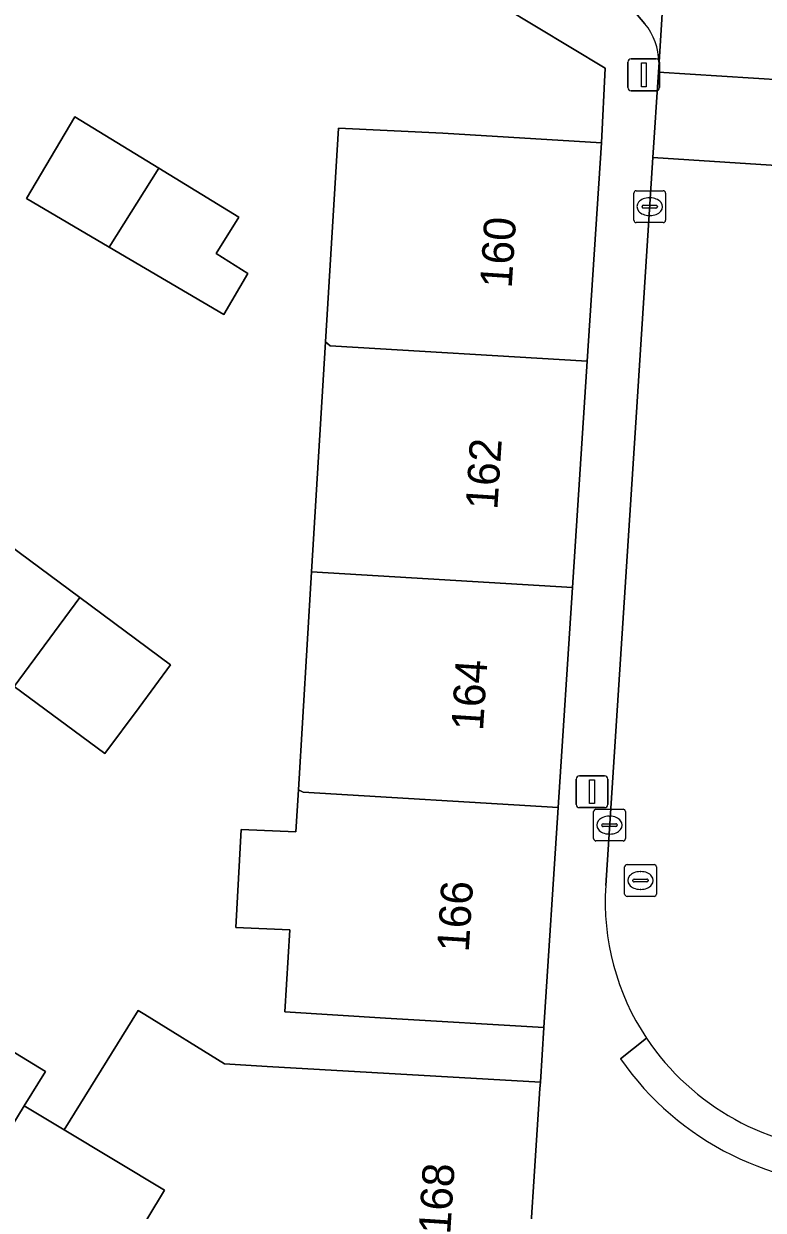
# Model space of a CAD drawing. Extents: x 160102 to 160934, y 382045 to 382923.
# Drawn here: x 160536.3 to 160559.57, y 382504.65 to 382542.01 of the extents above; entities that cross this region are included whole.
import ezdxf

# ---------------------------------------------------------------- set-up
doc = ezdxf.new("R2010")
doc.units = 0
for name, color, linetype in [('IMGEO_Erf', 7, 'Continuous'), ('IMGEO_Kolk', 7, 'Continuous'), ('IMGEO_Lichtmast', 7, 'Continuous'), ('IMGEO_Pand', 7, 'Continuous'), ('IMGEO_Pand_nummerreeks', 7, 'Continuous'), ('IMGEO_Parkeervlak_open', 7, 'Continuous'), ('IMGEO_Rijbaan_lokaal_open', 7, 'Continuous'), ('IMGEO_Rioolput', 7, 'Continuous'), ('IMGEO_Voetpad_open', 7, 'Continuous')]:
    doc.layers.add(name, color=color, linetype=linetype)

msp = doc.modelspace()

# ---------------------------------------------------------------- linework, layer by layer
at = {"layer": 'IMGEO_Erf'}
for points in [[(160544.676, 382513.487), (160542.97, 382513.555), (160543.147, 382516.638), (160544.862, 382516.571), (160544.942, 382517.894), (160545.358, 382524.757), (160545.796, 382532), (160546.203, 382538.72), (160549.487, 382538.567), (160554.477, 382538.267), (160554.602, 382540.614), (160550.277, 382543.226)], [(160533.952, 382510.872), (160536.981, 382509.028), (160536.316, 382507.94), (160537.577, 382507.182), (160539.903, 382510.942), (160540.111, 382510.813), (160542.623, 382509.26), (160543.965, 382509.183), (160552.558, 382508.69), (160552.672, 382510.406), (160547.682, 382510.707), (160544.519, 382510.898), (160544.676, 382513.487)]]:
    msp.add_lwpolyline(points, dxfattribs=at)
for points in [[(160536.39, 382536.513), (160537.908, 382539.086), (160540.55, 382537.465), (160543.07, 382535.92), (160542.351, 382534.777), (160543.356, 382534.145), (160542.594, 382532.854), (160538.987, 382534.981)], [(160533.142, 382523.268), (160534.176, 382524.662), (160535.214, 382526.061), (160538.069, 382523.943), (160540.923, 382521.825), (160539.928, 382520.484), (160538.851, 382519.032), (160535.996, 382521.15)]]:
    msp.add_lwpolyline(points, close=True, dxfattribs=at)
at = {"layer": 'IMGEO_Kolk'}
for p, q in [((160555.573, 382536.753), (160556.425, 382536.753)), ((160555.498, 382535.827), (160555.498, 382536.679)), ((160555.986, 382536.533), (160556.011, 382536.533)), ((160556.499, 382536.679), (160556.499, 382535.827)), ((160555.757, 382536.247), (160555.757, 382536.259)), ((160556.195, 382536.21), (160555.797, 382536.21)), ((160555.8, 382536.296), (160556.198, 382536.296)), ((160556.009, 382535.973), (160555.984, 382535.973)), ((160556.241, 382536.259), (160556.241, 382536.247)), ((160556.425, 382535.753), (160555.573, 382535.753)), ((160554.308, 382517.281), (160555.16, 382517.281)), ((160554.233, 382516.355), (160554.233, 382517.207)), ((160554.721, 382517.061), (160554.746, 382517.061)), ((160555.234, 382517.207), (160555.234, 382516.355)), ((160554.492, 382516.775), (160554.492, 382516.787)), ((160554.93, 382516.738), (160554.532, 382516.738)), ((160554.535, 382516.824), (160554.933, 382516.824)), ((160554.976, 382516.787), (160554.976, 382516.775)), ((160555.16, 382516.281), (160554.308, 382516.281)), ((160554.744, 382516.501), (160554.719, 382516.501))]:
    msp.add_line(p, q, dxfattribs=at)
for points in [[(160555.573, 382536.753), (160556.425, 382536.753)], [(160555.498, 382535.827), (160555.498, 382536.679)], [(160556.499, 382536.679), (160556.499, 382535.827)], [(160556.425, 382535.753), (160555.573, 382535.753)], [(160554.308, 382517.281), (160555.16, 382517.281)], [(160554.233, 382516.355), (160554.233, 382517.207)], [(160555.234, 382517.207), (160555.234, 382516.355)], [(160555.16, 382516.281), (160554.308, 382516.281)]]:
    msp.add_lwpolyline(points, dxfattribs=at)
for centre, radius, start, end in [((160555.575, 382536.677), 0.0765, 91.552, 178.448), ((160555.575, 382536.677), 0.0765, 91.552, 178.448), ((160556.423, 382536.677), 0.0765, 1.552, 88.448), ((160556.423, 382536.677), 0.0765, 1.552, 88.448), ((160555.797, 382536.256), 0.0403, 85.8775, 175.7526), ((160555.794, 382536.246), 0.0366, 178.938, 274.7102), ((160556.198, 382536.253), 0.043, 264.8664, 352.4533), ((160556.202, 382536.258), 0.0386, 1.7309, 96.639), ((160555.575, 382535.829), 0.0765, 181.552, 268.448), ((160555.575, 382535.829), 0.0765, 181.552, 268.448), ((160556.423, 382535.829), 0.0765, 271.552, 358.448), ((160556.423, 382535.829), 0.0765, 271.552, 358.448), ((160554.31, 382517.205), 0.0765, 91.552, 178.448), ((160554.31, 382517.205), 0.0765, 91.552, 178.448), ((160555.158, 382517.205), 0.0765, 1.552, 88.448), ((160555.158, 382517.205), 0.0765, 1.552, 88.448), ((160554.532, 382516.784), 0.0403, 85.8775, 175.7526), ((160554.529, 382516.774), 0.0366, 178.938, 274.7102), ((160554.933, 382516.781), 0.043, 264.8664, 352.4533), ((160554.937, 382516.786), 0.0386, 1.7309, 96.639), ((160554.31, 382516.357), 0.0765, 181.552, 268.448), ((160554.31, 382516.357), 0.0765, 181.552, 268.448), ((160555.158, 382516.357), 0.0765, 271.552, 358.448), ((160555.158, 382516.357), 0.0765, 271.552, 358.448)]:
    msp.add_arc(centre, radius, start, end, dxfattribs=at)
for centre, major_axis, ratio, start_param, end_param in [((160555.985, 382536.253), (-0.387, 0.002), 0.722429, 4.712389, 7.853982), ((160556.01, 382536.253), (-0.39, 0.002), 0.717154, 1.570796, 4.712389), ((160554.72, 382516.781), (-0.387, 0.002), 0.722429, 4.712389, 7.853982), ((160554.745, 382516.781), (-0.39, 0.002), 0.717154, 1.570796, 4.712389)]:
    msp.add_ellipse(centre, major_axis=major_axis, ratio=ratio, start_param=start_param, end_param=end_param, dxfattribs=at)
at = {"layer": 'IMGEO_Lichtmast'}
for p, q in [((160555.315, 382540.005), (160555.315, 382540.805)), ((160555.315, 382540.805), (160555.315, 382540.005)), ((160555.415, 382540.905), (160556.205, 382540.905)), ((160556.205, 382540.905), (160555.415, 382540.905)), ((160556.305, 382540.805), (160556.305, 382540.005)), ((160556.305, 382540.005), (160556.305, 382540.805)), ((160556.205, 382539.905), (160555.415, 382539.905)), ((160555.415, 382539.905), (160556.205, 382539.905)), ((160553.688, 382517.432), (160553.688, 382518.232)), ((160553.688, 382518.232), (160553.688, 382517.432)), ((160553.788, 382518.332), (160554.578, 382518.332)), ((160554.578, 382518.332), (160553.788, 382518.332)), ((160554.678, 382518.232), (160554.678, 382517.432)), ((160554.678, 382517.432), (160554.678, 382518.232)), ((160554.578, 382517.332), (160553.788, 382517.332)), ((160553.788, 382517.332), (160554.578, 382517.332))]:
    msp.add_line(p, q, dxfattribs=at)
for points in [[(160555.735, 382540.78), (160555.885, 382540.78), (160555.885, 382540.03), (160555.735, 382540.03), (160555.735, 382540.78)], [(160554.108, 382518.207), (160554.258, 382518.207), (160554.258, 382517.457), (160554.108, 382517.457), (160554.108, 382518.207)]]:
    msp.add_lwpolyline(points, dxfattribs=at)
for centre, start, end in [((160555.415, 382540.805), 90, 180), ((160555.415, 382540.805), 90, 180), ((160556.205, 382540.805), 0, 90), ((160556.205, 382540.805), 360, 90), ((160555.415, 382540.005), 180, 270), ((160555.415, 382540.005), 180, 270), ((160556.205, 382540.005), 270, 0), ((160556.205, 382540.005), 270, 0), ((160553.788, 382518.232), 90, 180), ((160553.788, 382518.232), 90, 180), ((160554.578, 382518.232), 0, 90), ((160554.578, 382518.232), 360, 90), ((160553.788, 382517.432), 180, 270), ((160553.788, 382517.432), 180, 270), ((160554.578, 382517.432), 270, 0), ((160554.578, 382517.432), 270, 0)]:
    msp.add_arc(centre, 0.1, start, end, dxfattribs=at)
at = {"layer": 'IMGEO_Pand'}
for points in [[(160538.987, 382534.981), (160540.55, 382537.465), (160537.908, 382539.086), (160536.39, 382536.513)], [(160554.477, 382538.267), (160549.487, 382538.567), (160546.203, 382538.72), (160545.796, 382532), (160545.938, 382531.875), (160554.031, 382531.388)], [(160538.987, 382534.981), (160542.594, 382532.854), (160543.356, 382534.145), (160542.351, 382534.777), (160543.07, 382535.92), (160540.55, 382537.465)], [(160554.031, 382531.388), (160545.938, 382531.875), (160545.796, 382532), (160545.358, 382524.757), (160553.57, 382524.261)], [(160538.069, 382523.943), (160535.214, 382526.061), (160534.176, 382524.662), (160533.142, 382523.268), (160535.996, 382521.15)], [(160553.57, 382524.261), (160545.358, 382524.757), (160544.942, 382517.894), (160545.09, 382517.821), (160553.121, 382517.336)], [(160540.923, 382521.825), (160538.069, 382523.943), (160535.996, 382521.15), (160538.851, 382519.032), (160539.928, 382520.484)], [(160553.121, 382517.336), (160545.09, 382517.821), (160544.942, 382517.894), (160544.862, 382516.571), (160543.147, 382516.638), (160542.97, 382513.555), (160544.676, 382513.487), (160544.519, 382510.898), (160547.682, 382510.707), (160552.672, 382510.406)], [(160552.545, 382508.49), (160552.558, 382508.69), (160543.965, 382509.183), (160542.623, 382509.26), (160540.111, 382510.813), (160539.903, 382510.942), (160537.577, 382507.182), (160540.727, 382505.291), (160539.679, 382503.544), (160541.371, 382502.756), (160541.507, 382502.748), (160543.903, 382502.6), (160543.88, 382502.225), (160544.098, 382502.211), (160544.087, 382502.042), (160552.091, 382501.5)], [(160536.981, 382509.028), (160533.952, 382510.872), (160532.291, 382508.224), (160535.085, 382506.529), (160535.354, 382506.366), (160536.316, 382507.94)], [(160537.577, 382507.182), (160536.316, 382507.94), (160535.354, 382506.366), (160535.085, 382506.529), (160534.306, 382505.245), (160538.993, 382502.401), (160539.679, 382503.544), (160540.727, 382505.291)]]:
    msp.add_lwpolyline(points, close=True, dxfattribs=at)
at = {"layer": 'IMGEO_Parkeervlak_open'}
for points in [[(160556.291, 382540.798), (160558.072, 382569.42)], [(160554.93, 382543.102), (160555.849, 382542.013)]]:
    msp.add_lwpolyline(points, dxfattribs=at)
msp.add_arc((160554.275, 382540.753), 2.016, 1.2884, 38.693, dxfattribs=at)
at = {"layer": 'IMGEO_Rijbaan_lokaal_open'}
for points in [[(160556.271, 382540.489), (160562.258, 382540.108), (160564.68, 382581.638), (160558.845, 382582.037), (160558.793, 382580.934), (160558.072, 382569.42), (160556.291, 382540.798)], [(160556.271, 382540.489), (160556.099, 382537.796), (160562.086, 382537.415), (160562.258, 382540.108)]]:
    msp.add_lwpolyline(points, close=True, dxfattribs=at)
msp.add_lwpolyline([(160560.981, 382520.071), (160562.086, 382537.415), (160556.099, 382537.796), (160555.566, 382529.462), (160554.615, 382514.878)], dxfattribs=at)
for centre, radius, start, end in [((160562.378, 382514.373), 7.779, 176.2803, 213.5691), ((160562.563, 382514.541), 8.026, 213.8343, 268.175)]:
    msp.add_arc(centre, radius, start, end, dxfattribs=at)
at = {"layer": 'IMGEO_Rioolput'}
for p, q in [((160555.209, 382514.612), (160555.209, 382515.464)), ((160555.284, 382515.538), (160556.136, 382515.538)), ((160556.21, 382515.464), (160556.21, 382514.612)), ((160555.468, 382515.032), (160555.468, 382515.044)), ((160555.511, 382515.081), (160555.909, 382515.081)), ((160555.697, 382515.318), (160555.722, 382515.318)), ((160555.952, 382515.044), (160555.952, 382515.032)), ((160555.906, 382514.995), (160555.508, 382514.995)), ((160555.72, 382514.758), (160555.695, 382514.758)), ((160556.136, 382514.538), (160555.284, 382514.538))]:
    msp.add_line(p, q, dxfattribs=at)
for points in [[(160555.209, 382514.612), (160555.209, 382515.464)], [(160555.284, 382515.538), (160556.136, 382515.538)], [(160556.21, 382515.464), (160556.21, 382514.612)], [(160556.136, 382514.538), (160555.284, 382514.538)]]:
    msp.add_lwpolyline(points, dxfattribs=at)
for centre, radius, start, end in [((160555.286, 382515.462), 0.0765, 91.552, 178.448), ((160555.286, 382515.462), 0.0765, 91.552, 178.448), ((160556.134, 382515.462), 0.0765, 1.552, 88.448), ((160556.134, 382515.462), 0.0765, 1.552, 88.448), ((160555.508, 382515.041), 0.0403, 85.8775, 175.7526), ((160555.505, 382515.031), 0.0366, 178.938, 274.7102), ((160555.909, 382515.038), 0.043, 264.8664, 352.4533), ((160555.913, 382515.043), 0.0386, 1.7309, 96.639), ((160555.286, 382514.614), 0.0765, 181.552, 268.448), ((160555.286, 382514.614), 0.0765, 181.552, 268.448), ((160556.134, 382514.614), 0.0765, 271.552, 358.448), ((160556.134, 382514.614), 0.0765, 271.552, 358.448)]:
    msp.add_arc(centre, radius, start, end, dxfattribs=at)
for centre, major_axis, ratio, start_param, end_param in [((160555.696, 382515.038), (-0.387, 0.002), 0.722429, 4.712389, 7.853982), ((160555.721, 382515.038), (-0.39, 0.002), 0.717154, 1.570796, 4.712389)]:
    msp.add_ellipse(centre, major_axis=major_axis, ratio=ratio, start_param=start_param, end_param=end_param, dxfattribs=at)
at = {"layer": 'IMGEO_Voetpad_open'}
for points in [[(160556.132, 382586.617), (160557.538, 382586.493), (160557.335, 382584.697), (160556.273, 382576.99), (160555.417, 382570.78), (160552.74, 382571.149), (160552.564, 382569.329), (160552.04, 382562.601), (160551.827, 382561.414), (160551.24, 382555.455), (160550.643, 382549.403), (160550.406, 382547), (160550.574, 382546.994), (160550.277, 382543.226), (160554.602, 382540.614), (160554.477, 382538.267), (160554.031, 382531.388), (160553.57, 382524.261), (160553.121, 382517.336), (160552.672, 382510.406), (160552.558, 382508.69), (160552.545, 382508.49), (160552.091, 382501.5)], [(160555.849, 382542.013), (160554.93, 382543.102)], [(160554.615, 382514.878), (160555.566, 382529.462), (160556.099, 382537.796), (160556.271, 382540.489), (160556.291, 382540.798)], [(160555.896, 382510.072), (160555.083, 382509.419)], [(160555.083, 382509.419), (160555.896, 382510.072)]]:
    msp.add_lwpolyline(points, dxfattribs=at)
for centre, radius, start, end in [((160554.275, 382540.753), 2.016, 1.2884, 38.693), ((160562.378, 382514.373), 7.779, 176.2803, 213.5691), ((160562.563, 382514.541), 8.026, 213.8343, 268.175), ((160562.714, 382514.713), 9.287, 214.7481, 272.3566), ((160562.714, 382514.713), 9.287, 214.7481, 272.3566)]:
    msp.add_arc(centre, radius, start, end, dxfattribs=at)

# ---------------------------------------------------------------- texts
at = {"layer": 'IMGEO_Pand_nummerreeks'}
for s, rotation, p in [('160', 86.2932, (160551.653, 382533.667)), ('162', 86.2932, (160551.202, 382526.696)), ('164', 86.2932, (160550.751, 382519.732)), ('166', 86.2932, (160550.301, 382512.767)), ('168', 86.2817, (160549.72, 382503.878))]:
    msp.add_text(s, height=1, rotation=rotation, dxfattribs=at).set_placement(p)

doc.saveas('drawing.dxf')
